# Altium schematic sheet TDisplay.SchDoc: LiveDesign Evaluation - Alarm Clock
size A3; Organization: Altium Limited; Address1: L3, 12a Rodborough Rd; Address2: Frenchs Forest; Address3: NSW; Address4: Australia 2086; DocumentNumber: 2; SheetNumber: 2; SheetTotal: 10
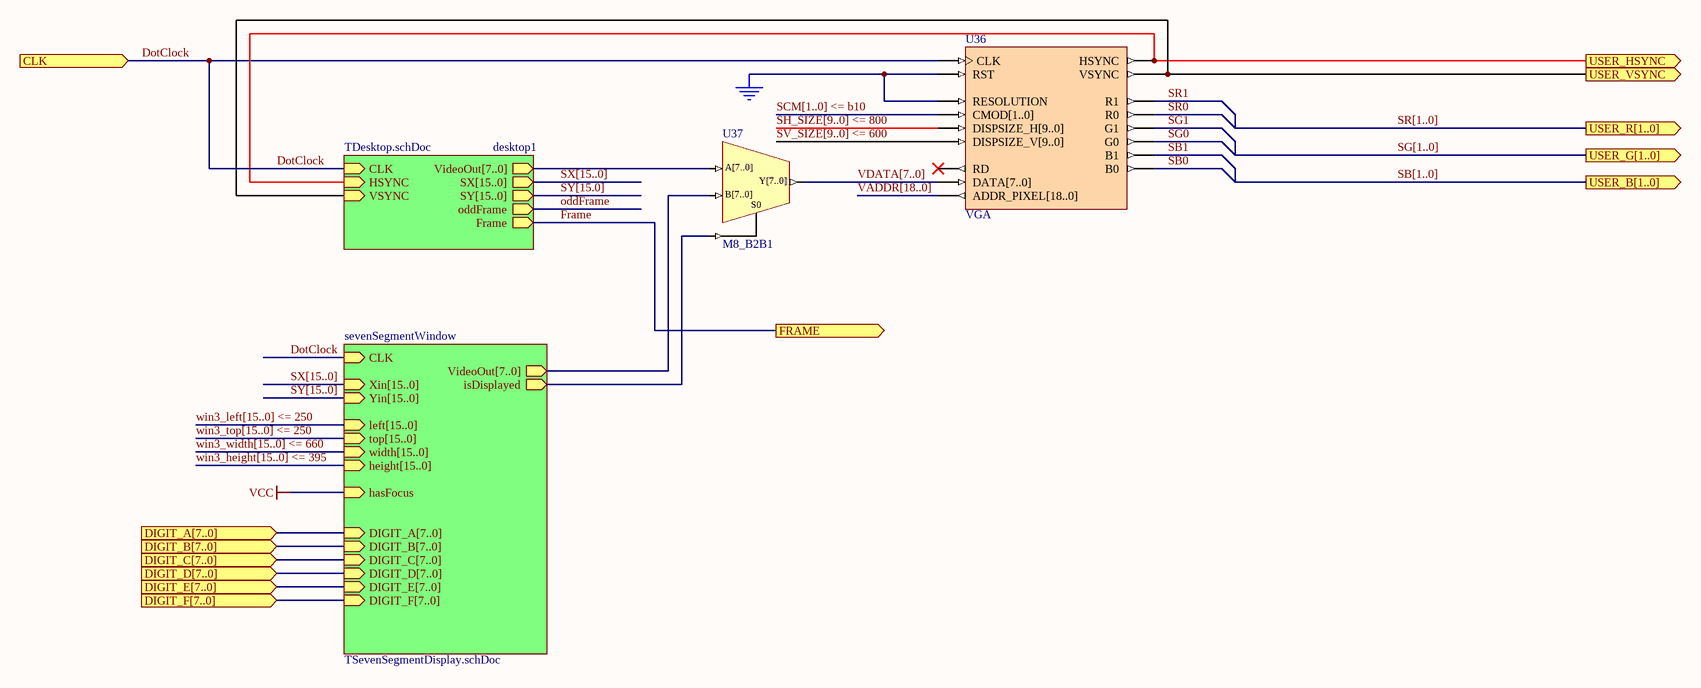
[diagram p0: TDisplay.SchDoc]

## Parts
U36  VGA
U37  M8_B2B1

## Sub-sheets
desktop1 = TDesktop.schDoc: CLK (in), VideoOut[7..0] (out), SX[15..0] (out), SY[15..0] (out), HSYNC (in), VSYNC (in), Frame (out), oddFrame (out)
sevenSegmentWindow = TSevenSegmentDisplay.schDoc: CLK (in), VideoOut[7..0] (out), Xin[15..0] (in), Yin[15..0] (in), top[15..0] (in), width[15..0] (in), height[15..0] (in), left[15..0] (in), DIGIT_A[7..0] (in), isDisplayed (out), hasFocus (in), DIGIT_B[7..0] (in), DIGIT_C[7..0] (in), DIGIT_D[7..0] (in), DIGIT_E[7..0] (in), DIGIT_F[7..0] (in)

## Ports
CLK (in), DIGIT_A[7..0] (in), DIGIT_B[7..0] (in), DIGIT_C[7..0] (in), DIGIT_D[7..0] (in), DIGIT_E[7..0] (in), DIGIT_F[7..0] (in), FRAME (out), USER_B[1..0] (out), USER_G[1..0] (out), USER_HSYNC (out), USER_R[1..0] (out), USER_VSYNC (out)

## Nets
GND: U36.RESOLUTION U36.RST
DotClock: U36.CLK ; port CLK, sheet sevenSegmentWindow/CLK, sheet desktop1/CLK
Frame: port FRAME, sheet desktop1/Frame
SB0: U36.B0
SB1: U36.B1
SG0: U36.G0
SG1: U36.G1
SR0: U36.R0
SR1: U36.R1
USER_HSYNC: U36.HSYNC ; port USER_HSYNC, sheet desktop1/HSYNC
USER_VSYNC: U36.VSYNC ; port USER_VSYNC, sheet desktop1/VSYNC
NetU37_S0: U37.S0 ; sheet sevenSegmentWindow/isDisplayed

Not connected (* = marked no-connect by the designer): U36 ADDR_PIXEL[18..0] CMOD[1..0] DATA[7..0] DISPSIZE_H[9..0] DISPSIZE_V[9..0] RD*; U37 A[7..0] B[7..0] Y[7..0]

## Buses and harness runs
bus port DIGIT_A[7..0] = sheet sevenSegmentWindow/DIGIT_A[7..0]
bus port DIGIT_B[7..0] = sheet sevenSegmentWindow/DIGIT_B[7..0]
bus port DIGIT_C[7..0] = sheet sevenSegmentWindow/DIGIT_C[7..0]
bus port DIGIT_D[7..0] = sheet sevenSegmentWindow/DIGIT_D[7..0]
bus port DIGIT_E[7..0] = sheet sevenSegmentWindow/DIGIT_E[7..0]
bus port DIGIT_F[7..0] = sheet sevenSegmentWindow/DIGIT_F[7..0]
bus SB[1..0] = port USER_B[1..0]
bus SCM[1..0] <= b10
bus SG[1..0] = port USER_G[1..0]
bus SH_SIZE[9..0] <= 800
bus SR[1..0] = port USER_R[1..0]
bus SV_SIZE[9..0] <= 600
bus SX[15..0] = sheet desktop1/SX[15..0]
bus SX[15..0] = sheet sevenSegmentWindow/Xin[15..0]
bus SY[15.0] = sheet desktop1/SY[15..0]
bus SY[15..0] = sheet sevenSegmentWindow/Yin[15..0]
bus VADDR[18..0]
bus VDATA[7..0]
bus win3_height[15..0] <= 395 = sheet sevenSegmentWindow/height[15..0]
bus win3_left[15..0] <= 250 = sheet sevenSegmentWindow/left[15..0]
bus win3_top[15..0] <= 250 = sheet sevenSegmentWindow/top[15..0]
bus win3_width[15..0] <= 660 = sheet sevenSegmentWindow/width[15..0]

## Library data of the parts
U36 = VGA: VGA Controller
U37 = M8_B2B1: 2x8-Bit Bus to 1x8-Bit Bus Multiplexer; ArchiveName: GENERIC; VHDLIB_SIM: GENERIC_LIB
